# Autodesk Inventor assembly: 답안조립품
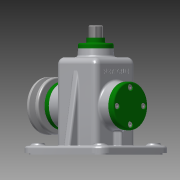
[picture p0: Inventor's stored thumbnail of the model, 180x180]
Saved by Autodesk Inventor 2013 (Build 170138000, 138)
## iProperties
Created: 2016-01
Part Number: 답안조립품
Document SubType Name: Assembly
Designer: User
Author: User
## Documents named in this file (18)
- C:\Users\User\Desktop\460126V1005\답안조립품.iam
- C:\Users\User\Desktop\460126V1005\본체.ipt
- C:\Users\User\Desktop\460126V1005\뒤커버.ipt
- C:\Users\User\Desktop\460126V1005\앞커버.ipt
- C:\Users\User\Desktop\460126V1005\편심축.ipt
- C:\Users\User\Desktop\460126V1005\베어링 15 x 35 x 11.ipt
- C:\Users\User\Desktop\460126V1005\멈춤링 15 x 1.ipt
- C:\Users\User\Desktop\460126V1005\슬라이드바.ipt
- C:\Users\User\Desktop\460126V1005\고정핀.ipt
- C:\Users\User\Desktop\460126V1005\멈춤링 6 x 5.ipt
- C:\Users\User\Desktop\460126V1005\상부부시.ipt
- C:\Users\User\Desktop\460126V1005\링크.ipt
- C:\Users\User\Desktop\460126V1005\키 5 x 5 x 14.ipt
- C:\Users\User\Desktop\460126V1005\와셔.ipt
- C:\Users\User\Desktop\460126V1005\볼트 M4 x 10.ipt
- C:\Users\User\Desktop\460126V1005\볼트 M3 x 8.ipt
- C:\Users\User\Desktop\460126V1005\V-벨트풀리.ipt
- C:\Users\User\Desktop\460126V1005\볼트 M6 x 12.ipt
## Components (15 placed, 5 different names)
1. 고정핀:1
2. V-벨트풀리:1
3. ISO 4018 M6 x 12:1
4. ISO 4762 M4 x 10:2
5. ISO 4762 M4 x 10:3
6. ISO 4762 M4 x 10:4
7. ISO 4762 M4 x 10:5
8. ISO 4762 M4 x 10:1
9. ISO 4762 M4 x 10:6
10. ISO 4762 M4 x 10:7
11. ISO 4762 M4 x 10:8
12. ISO 4762 M3 x 8:1
13. ISO 4762 M3 x 8:2
14. ISO 4762 M3 x 8:3
15. ISO 4762 M3 x 8:4
